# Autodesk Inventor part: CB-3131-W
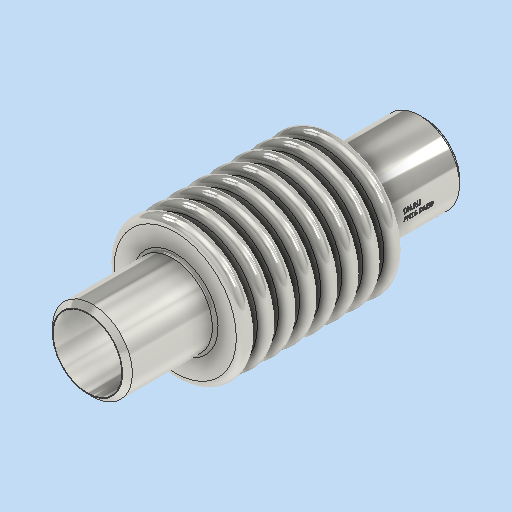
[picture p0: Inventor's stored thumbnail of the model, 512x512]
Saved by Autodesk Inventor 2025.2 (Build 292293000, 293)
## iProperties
Company: DN.RU
Created: 2026-04
Part Number: CB-3131-W
Material: Типовые
Document SubType Name: Modeling
Designer: DN.RU
Density: 3.99329 g/cm^3
Appearance: По умолчанию
Description: D140-02130
Mass: 600 g
Surface Area: 1981.31 cm^2
Volume: 150.252 cm^3
Author: DN.RU
Title: Компенсатор сильфонный осевой DN.ru Ду50 Ру16
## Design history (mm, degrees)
sketch "Эскиз1"
  geometry: L1 (0, 0)-(0, -120); L2 (28.5, -120)-(28.5, 0); L3 (28.5, 0)-(0, 0); L4 (28.5, 0)-(28.5, -7.5); L5 (13.5, -7.5)-(43.5, -7.5); L6 (13.5, -12.5)-(43.5, -12.5); L7 (43.5, -2.5)-(13.5, -2.5); L8 (43.5, -11.5)-(13.5, -11.5); L9 (13.5, -3.5)-(43.5, -3.5); L10 (43.5, -17.5)-(13.5, -17.5); L11 (13.5, -18.5)-(43.5, -18.5); L12 (13.5, -22.5)-(43.5, -22.5); L13 (13.5, -27.5)-(43.5, -27.5); L14 (43.5, -26.5)-(13.5, -26.5); L15 (43.5, -32.5)-(13.5, -32.5); L16 (13.5, -33.5)-(43.5, -33.5); L17 (13.5, -37.5)-(43.5, -37.5); L18 (13.5, -42.5)-(43.5, -42.5); L19 (43.5, -41.5)-(13.5, -41.5); L20 (43.5, -47.5)-(13.5, -47.5); L21 (13.5, -48.5)-(43.5, -48.5); L22 (13.5, -52.5)-(43.5, -52.5); L23 (13.5, -57.5)-(43.5, -57.5); L24 (43.5, -56.5)-(13.5, -56.5); L25 (0, -120)-(28.5, -120); L26 (28.5, -120)-(24.5, -120); L27 (28.5, -47.5)-(27.5, -47.5); L28 (24.5, -120)-(24.5, -56.5); L29 (28.5, -48.5)-(27.5, -48.5); L30 (27.5, -48.5)-(27.5, -41.5); L31 (28.5, -33.5)-(27.5, -33.5); L32 (27.5, -33.5)-(27.5, -26.5); L33 (28.5, -18.5)-(27.5, -18.5); L34 (27.5, -18.5)-(27.5, -11.5); L35 (28.5, -3.5)-(27.5, -3.5); L36 (27.5, -3.5)-(27.5, 0); A1 r 5 centre (13.5, -7.5) between (13.5, -2.5) and (13.5, -12.5); A2 r 5 centre (43.5, -7.5) between (43.5, -12.5) and (43.5, -2.5); A3 r 4 centre (13.5, -7.5) between (13.5, -3.5) and (13.5, -11.5); A4 r 4 centre (43.5, -7.5) between (43.5, -11.5) and (43.5, -3.5); A5 r 4 centre (13.5, -22.5) between (13.5, -18.5) and (13.5, -26.5); A6 r 5 centre (13.5, -22.5) between (13.5, -17.5) and (13.5, -27.5); A7 r 4 centre (43.5, -22.5) between (43.5, -26.5) and (43.5, -18.5); A8 r 5 centre (43.5, -22.5) between (43.5, -27.5) and (43.5, -17.5); A9 r 4 centre (13.5, -37.5) between (13.5, -33.5) and (13.5, -41.5); A10 r 5 centre (13.5, -37.5) between (13.5, -32.5) and (13.5, -42.5); A11 r 4 centre (43.5, -37.5) between (43.5, -41.5) and (43.5, -33.5); A12 r 5 centre (43.5, -37.5) between (43.5, -42.5) and (43.5, -32.5); A13 r 4 centre (13.5, -52.5) between (13.5, -48.5) and (13.5, -56.5); A14 r 5 centre (13.5, -52.5) between (13.5, -47.5) and (13.5, -57.5); A15 r 4 centre (43.5, -52.5) between (43.5, -56.5) and (43.5, -48.5); A16 r 5 centre (43.5, -52.5) between (43.5, -57.5) and (43.5, -47.5); 18 further points
  constraints: 80 end point, 32 point on circle, 16 centre point, 15 point on line, 6 midpoint, 5 perpendicular, 4 tangent, 3 parallel, 2 vertical, 1 horizontal, 69 other
  dimensions: "d0" = 120 distance of L1.start L1.end; "d1" = 28.5 distance of L2.start L1.end; "d3" = 7.5 distance of L2.end L4.end; "d4" = 15 distance of L4.end L5.end; "d5" = 10 diameter of A2; "d6" = 1 distance between parallel lines of L6 L8; "d9" = 15 distance of L4.end point (28.5, -22.5); "d14" = 4 distance of L2.start L26.end; "d15" = 1 distance of L27.start L27.end; "d16" = 1 distance of L29.start L29.end; "d17" = 1 distance of L31.start L31.end; "d18" = 1 distance of L33.start L33.end; "d19" = 1 distance of L35.start L35.end
revolve "Вращение1" sketch "Эскиз1" stored, may be unused: angle "d20" = 90 deg
mirror "Зеркальное отражение1"
chamfer "Фаска1" distance "d21" = 3.5; stored, may be unused: second distance "d22" = 2, angle "d23" = 45 deg
fillet "Сопряжение1" dims "d24" = 2
node "РабПлоскость1"
sketch "Эскиз2"
  geometry: L1 (4.495, 11.929)-(4.495, -9.281); L2 (4.495, -9.281)-(-3.635, -9.281); L3 (-3.635, -9.281)-(-3.635, 11.929); L4 (-3.635, 11.929)-(4.495, 11.929); 1 further point
  constraints: 2 other
feature "Рельеф1" sketch "Эскиз2" dims "d25" = 0.1, "d26" = 0
node "Твердое тело1"
node "Эскиз — прямоугольный массив1" dims "d9" = 15, "d12" = 10
